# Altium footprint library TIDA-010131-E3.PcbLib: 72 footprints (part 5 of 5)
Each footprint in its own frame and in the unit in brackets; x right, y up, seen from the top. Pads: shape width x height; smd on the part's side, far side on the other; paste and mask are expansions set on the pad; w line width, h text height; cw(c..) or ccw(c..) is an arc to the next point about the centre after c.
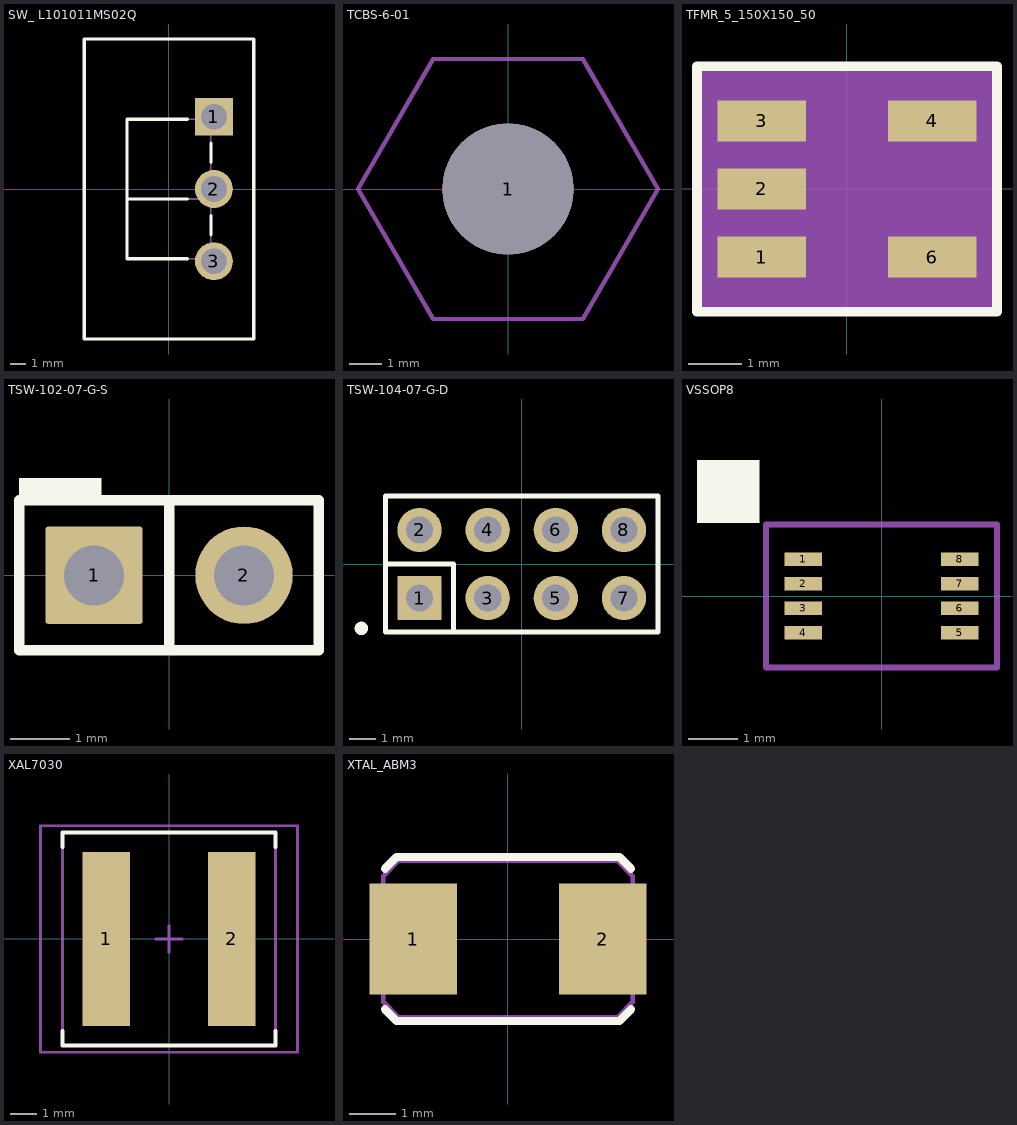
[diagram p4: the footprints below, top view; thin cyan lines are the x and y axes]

## SW_ L101011MS02Q [mm] "SWITCH SLIDE sPST 4A PCB"
height 14.18
pads (3):
  rect 2.416x2.416 hole 1.65: 1(2.857,4.6)
  round 2.416 hole 1.65: 2(2.857,0) 3(2.857,-4.6)
Top Overlay:
  lines w0.2: -5.405,9.55 5.395,9.55 5.395,-9.55 ; -5.395,9.55 -5.395,-9.55 5.405,-9.55 ; -2.668,-0.635 1.166,-0.635 ; 1.166,-4.445 -2.668,-4.445 -2.668,4.445 1.166,4.445 ; 2.668,-2.911 2.668,-1.689 ; 2.668,1.689 2.668,2.911
Mechanical 5:
  lines w0.1: -2.668,-0.635 2.668,-0.635 ; -2.668,-0.635 -2.668,4.445 2.668,4.445 2.668,-0.635 ; -2.668,-0.635 -2.668,-4.445 2.668,-4.445 2.668,-0.635 ; -5.395,-9.55 5.395,-9.55 5.395,9.55 -5.395,9.55 -5.395,-9.55
  text ".Designator" at -0.876,2.235 h1.02
3D body: height 14.18, standoff 9.1, extent -2.668,-0.635 2.668,4.445
3D body: height 9.1, standoff 0, extent -5.394,-9.549 5.394,9.549

## TCBS-6-01 [mil] "Richco Plastics"
height 375
pads (1):
  round 157 hole 157 unplated mask+10: 1(0,0)
Mechanical 5:
  lines w5: -179.57,0 -89.79,-155.51 89.78,-155.51 179.56,0 89.78,155.51 -89.79,155.51 -179.57,0
  text ".Designator" at -16.2,-12.7 h25
3D body "Richco_TCBS-6.stp": height 374.61, standoff -387.57, extent -179.57,-155.51 179.56,155.52

## TFMR_5_150X150_50 [mil] "TFMR_5_150X150_50"
pads (5):
  rect 65x30 smd: 1(-62.5,-50) 2(-62.5,0) 3(-62.5,50) 4(62.5,50) 6(62.5,-50)
Top Overlay:
  lines w7: -110,-90 -110,90 110,90 110,-90 -110,-90
  text ".Designator" at 4.72,108.94 h30
Mechanical 5:
  lines w1: -75,-75 -75,75 75,75 75,-75 -75,-75
  text "*" at -80,-48.33 h25
Mechanical 16:
  region: 110,-90 -110,-90 -110,90 110,90
Mechanical 27:
  text "3" at -52.5,50 h25
  text "1" at -52.5,-50 h25
  text "6" at 72.5,-50 h25
  text "4" at 72.5,50 h25
  text "2" at -52.5,0 h25

## TSW-102-07-G-S [mm] "Samtec 100mil, 1x2, 230 mil above insulator"
height 8.382
pads (2):
  rrect6% 1.65x1.65 hole 1.016: 1(-1.27,0)
  round 1.65 hole 1.016: 2(1.27,0)
Top Overlay:
  rectangle: -2.54,1.27 -1.143,1.651
  lines w0.178: 0,-1.27 0,1.27 ; -2.54,-1.27 -2.54,1.27 2.54,1.27 2.54,-1.27 -2.54,-1.27
Mechanical 5:
  lines w0.127: -2.54,-1.27 2.54,-1.27 2.54,1.27 -2.54,1.27 -2.54,-1.27
  text ".Designator" at -1.524,-0.508 h0.64
3D body "SamtecTSW-07_2x1.stp": height 8.38, standoff -2.54, extent -2.54,-1.27 2.54,1.27

## TSW-104-07-G-D [mm] "Samtec 100mil, 2x4, 230 mil above insulator"
height 8.382
pads (8):
  rrect6% 1.65x1.65 hole 1.016: 1(-3.81,-1.27)
  round 1.65 hole 1.016: 2(-3.81,1.27) 3(-1.27,-1.27) 4(-1.27,1.27) 5(1.27,-1.27) 6(1.27,1.27) 7(3.81,-1.27) 8(3.81,1.27)
Top Overlay:
  circle w0.25: c-5.98,-2.4 r0.125
  lines w0.178: -5.08,0 -2.54,0 -2.54,-2.54 ; -5.08,-2.54 -5.08,2.54 5.08,2.54 5.08,-2.54 -5.08,-2.54
Mechanical 5:
  rectangle: -4.318,-1.778 -3.302,-0.762
  lines w0.127: -5.08,-2.54 5.08,-2.54 5.08,2.54 -5.08,2.54 -5.08,-2.54
  text ".Designator" at -0.787,0.778 h0.64
3D body "SamtecTSW-07_4x2.stp": height 8.38, standoff -2.54, extent -5.08,-2.54 5.08,2.54

## VSSOP8 [mil]
pads (8):
  rect 30x11 smd: 1(-63,29.5) 2(-63,9.8) 3(-63,-9.9) 4(-63,-29.6) 5(63,-29.6) 6(63,-9.9) 7(63,9.8) 8(63,29.5)
Top Overlay:
  region: -148.43,59.06 -98.43,59.06 -98.43,109.06 -148.43,109.06
Mechanical 5:
  lines w5: -93,-57.5 92.9,-57.5 92.9,57.5 -93,57.5 -93,-57.5
  text "*" at -90,50 h30
  text ".Designator" at -38,-13.73 h25

## XAL7030 [mm] "Coilcraft XAL7030 7.5 x.7.5 x 3.1 mm"
height 3.1
pads (2):
  rect 1.78x6.55 smd: 1(-2.36,0) 2(2.36,0)
Top Overlay:
  lines w0.152: -4,-3.46 -4,-4 4,-4 4,-3.46 ; -4,3.46 -4,4 4,4 4,3.46
Mechanical 5:
  lines w0.1: -4,-4 -4,4 4,4 4,-4 -4,-4
  text ".Designator" at 0.229,-0.914 h0.64
Mechanical 15:
  lines w0.1: -0.5,0 0.5,0 ; 0,-0.5 0,0.5 ; -4.825,-4.25 -4.825,4.25 4.825,4.25 4.825,-4.25 -4.825,-4.25
3D body: height 3.1, standoff 0, extent -4,-4 4,4

## XTAL_ABM3 [mm] "Abracon recommended land pattern 12.28.10"
height 1.3
pads (2):
  rect 1.9x2.4 smd: 1(-2.05,0) 2(2.05,0)
Top Overlay:
  lines w0.178: -2.667,-1.524 -2.413,-1.778 0,-1.778 2.413,-1.778 2.667,-1.524 ; -2.667,1.524 -2.413,1.778 0,1.778 2.413,1.778 2.667,1.524
Mechanical 5:
  lines w0.1: -2.7,-1.364 -2.7,1.364 -2.364,1.7 2.364,1.7 2.7,1.364 2.7,-1.364 2.364,-1.7 -2.364,-1.7 -2.7,-1.364
  text ".Designator" at 0.724,0.328 h0.64
3D body "Abracon_ABM3.stp": height 1.3, standoff 0, extent -2.597,-1.698 2.603,1.702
